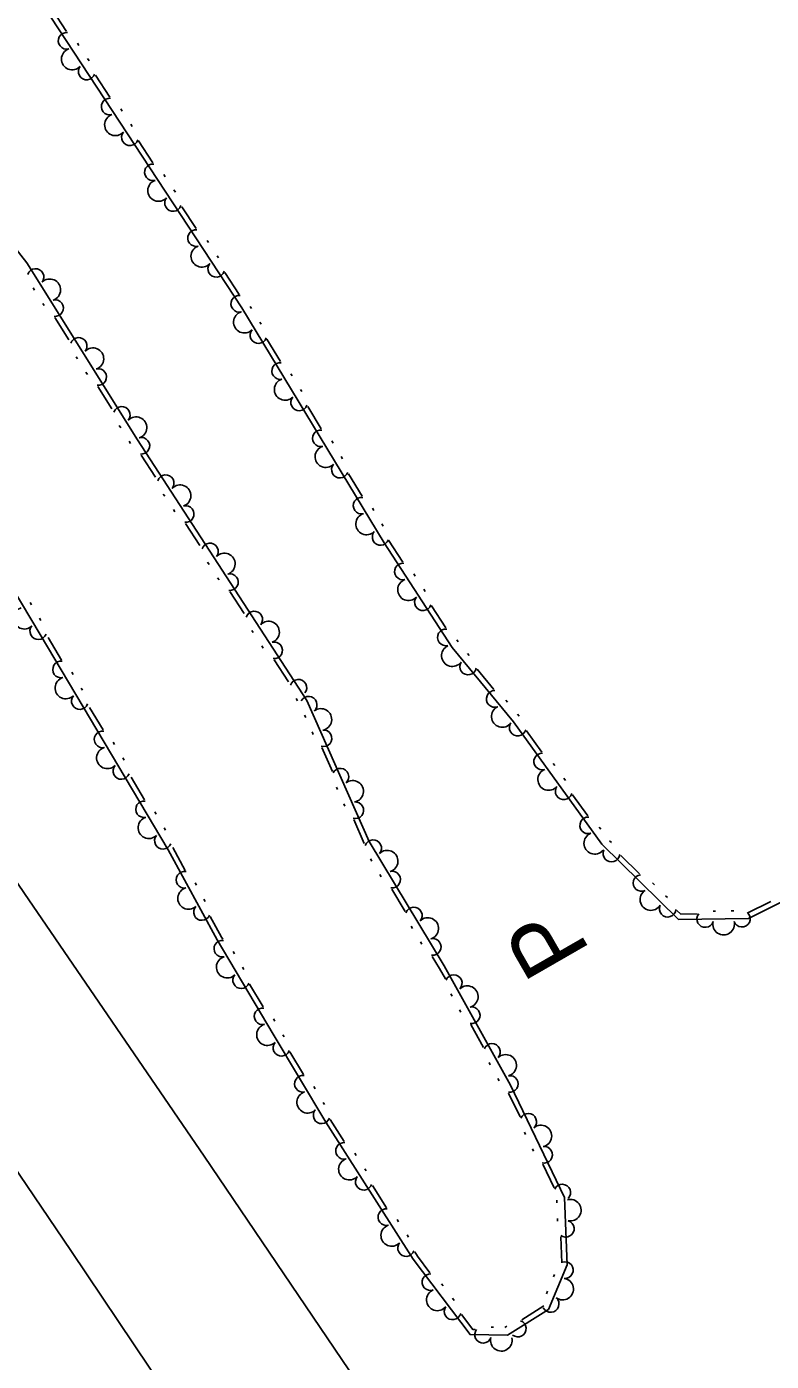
# Model space of a CAD drawing. Extents: x 2030130 to 2036320, y 723205 to 762423.
# Drawn here: x 2034304.6 to 2034421.1, y 759843.4 to 760052.2 of the extents above; entities that cross this region are included whole.
import ezdxf

# ---------------------------------------------------------------- set-up
doc = ezdxf.new("R2010")
doc.units = 0
for name, color, linetype in [('Draft_Station Labels Major', 7, 'Continuous'), ('Draft_Station Tics Major', 7, 'Continuous'), ('Prop Horizontal Alignment Ramp', 7, 'Continuous')]:
    doc.layers.add(name, color=color, linetype=linetype)

msp = doc.modelspace()

# ---------------------------------------------------------------- linework, layer by layer
at = {"layer": 'Draft_Station Labels Major'}
for p, q in [((2034332.4, 759875.51), (2034360.74, 759833.62)), ((2034311.52, 759860.74), (2034339.29, 759819.51))]:
    msp.add_line(p, q, dxfattribs=at)
for points in [[(2033718.38, 760730.67), (2033746.51, 760689.6), (2033774.62, 760648.49), (2033802.7, 760607.26), (2033830.67, 760566.06), (2033858.89, 760525.01), (2033886.8, 760483.79), (2033914.88, 760442.66), (2033945.45, 760397.69), (2033973.64, 760356.6), (2034001.68, 760315.42), (2034029.6, 760274.28), (2034057.68, 760233.24), (2034085.75, 760192.04), (2034113.77, 760150.87), (2034141.95, 760109.94), (2034159.83, 760083.11), (2034175.33, 760060.45), (2034197.95, 760027.35), (2034226.1, 759986.31), (2034253.95, 759945.01), (2034282.77, 759903.21), (2034311.52, 759860.74)], [(2034332.4, 759875.51), (2034304.28, 759916.6), (2034275.65, 759958.8), (2034247.14, 760000.6), (2034219.84, 760040.78), (2034191.61, 760081.68), (2034163.74, 760123.03), (2034135.88, 760163.98), (2034107.11, 760206.11), (2034080.34, 760245.23), (2034051.49, 760287.62), (2034022.91, 760329.48), (2033995.09, 760369.99), (2033966.89, 760411.11), (2033935.74, 760457.29), (2033907.97, 760498.26), (2033880.46, 760539.38), (2033851.33, 760582.23)]]:
    msp.add_lwpolyline(points, dxfattribs=at)
at = {"layer": 'Draft_Station Tics Major'}
for points in [[(2033865.22, 760655.09), (2033891.74, 760610.39), (2033928.27, 760560.61), (2033957.26, 760512.4), (2033990.84, 760466.46), (2034027.29, 760415.57), (2034062.79, 760367.8), (2034100.45, 760308.07), (2034126.3, 760269.13), (2034147.67, 760241.66), (2034171.15, 760213.5), (2034188.43, 760192.75), (2034201.98, 760164.61), (2034214.77, 760146.29), (2034228.35, 760126.12), (2034239.08, 760107.39), (2034248.43, 760090.51), (2034260.06, 760075.4), (2034270.93, 760058.37), (2034285.47, 760039.75), (2034304.65, 760015.27), (2034321.95, 759987.59), (2034348.43, 759946.8)], [(2033965.52, 760565.2), (2033991.66, 760525.26), (2034035.33, 760466.26), (2034077.67, 760405.45), (2034116.64, 760339.6), (2034163.46, 760272.17), (2034200.03, 760218.19), (2034231.88, 760166.87), (2034275.46, 760103.32), (2034304.79, 760059.28), (2034338.27, 760008.25), (2034360.54, 759971.46)], [(2034326.75, 759923.45), (2034306.73, 759957.16), (2034295.18, 759976.5), (2034283.32, 759994.79), (2034271.8, 760013.59), (2034263.7, 760033.69), (2034251.35, 760054.43), (2034226.75, 760080.43), (2034216.04, 760102), (2034205.31, 760120.49), (2034188.73, 760144.18), (2034176.71, 760159.19)], [(2034308.62, 760054.93), (2034310.87, 760051.5)], [(2034312.57, 760049.67), (2034312.79, 760049.32)], [(2034360.54, 759971.46), (2034371.18, 759955.13), (2034380.75, 759943.47), (2034394.56, 759924.33), (2034406.56, 759912.57), (2034417.47, 759912.7), (2034428.08, 759918.01), (2034440.63, 759926.81), (2034450.23, 759943), (2034456.78, 759958.6), (2034460.68, 759978.63), (2034471.11, 759991.86), (2034494.44, 760007.17), (2034510.43, 760028.22), (2034523.34, 760037.05), (2034542.05, 760043.12), (2034564.16, 760048.88), (2034589.7, 760042.02), (2034611.85, 760032.5), (2034630.07, 760020.88), (2034650.14, 760012.08), (2034662.68, 760016.57)], [(2034314.14, 760047.27), (2034314.37, 760046.92)], [(2034315.37, 760044.64), (2034317.62, 760041.21)], [(2034319.32, 760039.38), (2034319.54, 760039.04)], [(2034320.89, 760036.98), (2034321.12, 760036.64)], [(2034322.12, 760034.36), (2034324.37, 760030.93)], [(2034326.06, 760029.1), (2034326.29, 760028.75)], [(2034327.64, 760026.7), (2034327.87, 760026.35)], [(2034328.87, 760024.07), (2034331.12, 760020.64)], [(2034332.82, 760018.81), (2034333.04, 760018.47)], [(2034334.39, 760016.41), (2034334.62, 760016.06)], [(2034335.62, 760013.78), (2034337.87, 760010.36)], [(2034305.63, 760011.38), (2034305.85, 760011.03)], [(2034307.16, 760008.94), (2034307.37, 760008.6)], [(2034339.57, 760008.48), (2034339.79, 760008.12)], [(2034309.02, 760006.73), (2034311.2, 760003.25)], [(2034341.06, 760006.02), (2034341.27, 760005.67)], [(2034342.2, 760003.35), (2034344.32, 759999.84)], [(2034312.37, 760000.6), (2034312.59, 760000.25)], [(2034313.89, 759998.16), (2034314.11, 759997.82)], [(2034345.94, 759997.95), (2034346.16, 759997.6)], [(2034315.76, 759995.95), (2034317.94, 759992.47)], [(2034347.43, 759995.49), (2034347.64, 759995.14)], [(2034348.57, 759992.83), (2034350.69, 759989.32)], [(2034319.11, 759989.82), (2034319.33, 759989.47)], [(2034352.32, 759987.42), (2034352.53, 759987.07)], [(2034320.63, 759987.38), (2034320.85, 759987.04)], [(2034322.54, 759985.18), (2034324.78, 759981.74)], [(2034353.8, 759984.97), (2034354.01, 759984.62)], [(2034354.94, 759982.3), (2034357.06, 759978.79)], [(2034325.99, 759979.11), (2034326.22, 759978.76)], [(2034327.56, 759976.7), (2034327.78, 759976.35)], [(2034358.68, 759976.9), (2034358.9, 759976.55)], [(2034329.46, 759974.51), (2034331.7, 759971.07)], [(2034360.17, 759974.44), (2034360.38, 759974.09)], [(2034361.22, 759971.91), (2034363.46, 759968.47)], [(2034332.92, 759968.44), (2034333.14, 759968.1)], [(2034365.15, 759966.64), (2034365.37, 759966.29)], [(2034334.48, 759966.03), (2034334.7, 759965.69)], [(2034336.39, 759963.85), (2034338.62, 759960.41)], [(2034366.72, 759964.23), (2034366.94, 759963.89)], [(2034305.39, 759961.8), (2034305.18, 759962.15)], [(2034367.94, 759961.6), (2034370.18, 759958.17)], [(2034306.86, 759959.34), (2034306.65, 759959.69)], [(2034310.07, 759953.13), (2034307.98, 759956.66)], [(2034339.84, 759957.78), (2034340.06, 759957.43)], [(2034371.87, 759956.33), (2034372.09, 759955.99)], [(2034341.4, 759955.37), (2034341.62, 759955.02)], [(2034373.56, 759954.18), (2034373.82, 759953.86)], [(2034343.31, 759953.18), (2034345.54, 759949.74)], [(2034311.89, 759950.87), (2034311.68, 759951.23)], [(2034375.06, 759951.7), (2034377.66, 759948.53)], [(2034313.36, 759948.41), (2034313.15, 759948.76)], [(2034316.57, 759942.2), (2034314.47, 759945.73)], [(2034326.75, 759923.45), (2034334.39, 759909.37), (2034343.19, 759894.61), (2034351.39, 759880.82), (2034365.04, 759859.43), (2034373.96, 759847.6), (2034379.81, 759847.52), (2034386.21, 759851.55), (2034389.14, 759858.53), (2034388.74, 759869.08), (2034380.29, 759886.64), (2034369.91, 759905.3), (2034358.16, 759924.77), (2034348.43, 759946.8)], [(2034346.76, 759947.11), (2034346.98, 759946.77)], [(2034379.54, 759946.89), (2034379.8, 759946.57)], [(2034348.26, 759944.15), (2034348.09, 759944.52)], [(2034381.36, 759944.67), (2034381.62, 759944.35)], [(2034349.41, 759941.52), (2034349.25, 759941.9)], [(2034382.78, 759942.06), (2034385.18, 759938.73)], [(2034318.38, 759939.95), (2034318.17, 759940.3)], [(2034352.44, 759935.69), (2034350.78, 759939.44)], [(2034319.85, 759937.48), (2034319.64, 759937.83)], [(2034386.95, 759936.98), (2034387.19, 759936.65)], [(2034323.06, 759931.27), (2034320.97, 759934.8)], [(2034353.23, 759932.9), (2034353.06, 759933.27)], [(2034388.63, 759934.65), (2034388.87, 759934.32)], [(2034389.98, 759932.08), (2034392.38, 759928.76)], [(2034324.88, 759929.02), (2034324.67, 759929.37)], [(2034354.39, 759930.27), (2034354.22, 759930.65)], [(2034326.35, 759926.55), (2034326.14, 759926.9)], [(2034357.42, 759924.44), (2034355.76, 759928.19)], [(2034394.15, 759927), (2034394.39, 759926.67)], [(2034395.75, 759924.88), (2034396.05, 759924.6)], [(2034327.48, 759923.84), (2034329.43, 759920.24)], [(2034358.6, 759921.67), (2034358.38, 759922.03)], [(2034397.52, 759922.58), (2034400.45, 759919.71)], [(2034360.08, 759919.22), (2034359.87, 759919.57)], [(2034330.96, 759918.27), (2034331.16, 759917.91)], [(2034363.82, 759913.81), (2034361.7, 759917.32)], [(2034402.49, 759918.28), (2034402.78, 759917.99)], [(2034332.33, 759915.74), (2034332.53, 759915.39)], [(2034404.54, 759916.27), (2034404.83, 759915.98)], [(2034417.31, 759913.53), (2034420.97, 759915.37)], [(2034333.34, 759913.03), (2034335.1, 759909.78), (2034335.29, 759909.46)], [(2034406.3, 759913.97), (2034406.89, 759913.39), (2034409.49, 759913.42)], [(2034411.95, 759913.86), (2034412.36, 759913.87)], [(2034414.81, 759913.89), (2034415.22, 759913.9)], [(2034364.95, 759911.14), (2034364.74, 759911.49)], [(2034366.43, 759908.68), (2034366.22, 759909.03)], [(2034336.91, 759907.56), (2034337.11, 759907.2)], [(2034370.1, 759903.26), (2034369.2, 759904.89), (2034368.05, 759906.78)], [(2034338.38, 759905.09), (2034338.59, 759904.74)], [(2034339.49, 759902.41), (2034341.59, 759898.89)], [(2034371.14, 759900.56), (2034370.94, 759900.91)], [(2034372.53, 759898.05), (2034372.33, 759898.4)], [(2034343.2, 759896.99), (2034343.41, 759896.64)], [(2034376.08, 759892.51), (2034374.09, 759896.1)], [(2034344.67, 759894.52), (2034344.88, 759894.17)], [(2034345.79, 759891.84), (2034347.89, 759888.32)], [(2034377.12, 759889.8), (2034376.92, 759890.16)], [(2034378.52, 759887.3), (2034378.32, 759887.66)], [(2034349.5, 759886.41), (2034349.71, 759886.06)], [(2034381.77, 759881.67), (2034379.99, 759885.36)], [(2034350.96, 759883.94), (2034351.17, 759883.59)], [(2034352.09, 759881.25), (2034354.27, 759877.83)], [(2034382.65, 759878.9), (2034382.47, 759879.27)], [(2034355.94, 759875.98), (2034356.16, 759875.63)], [(2034383.89, 759876.32), (2034383.72, 759876.69)], [(2034357.48, 759873.56), (2034357.7, 759873.21)], [(2034387.11, 759870.58), (2034385.33, 759874.28)], [(2034358.68, 759870.92), (2034360.89, 759867.46)], [(2034387.54, 759868.22), (2034387.53, 759868.63)], [(2034362.56, 759865.61), (2034362.78, 759865.26)], [(2034387.65, 759865.35), (2034387.64, 759865.76)], [(2034364.1, 759863.19), (2034364.32, 759862.84)], [(2034388.31, 759858.81), (2034388.16, 759862.91)], [(2034365.3, 759860.55), (2034365.72, 759859.9), (2034367.68, 759857.29)], [(2034387.02, 759856.65), (2034387.18, 759857.03)], [(2034369.49, 759855.57), (2034369.74, 759855.25)], [(2034385.91, 759854), (2034386.06, 759854.38)], [(2034371.22, 759853.28), (2034371.47, 759852.95)], [(2034382.03, 759849.89), (2034385.5, 759852.08)], [(2034372.62, 759850.74), (2034374.38, 759848.42), (2034374.77, 759848.41)], [(2034377.23, 759848.79), (2034377.64, 759848.78)], [(2034379.39, 759848.71), (2034379.73, 759848.93)]]:
    msp.add_lwpolyline(points, dxfattribs=at)
for centre, radius, start, end in [((2034310.86, 760050.02), 1.3, 84.0412, 284.8378), ((2034311.75, 760047.17), 1.69, 109.2365, 317.309), ((2034314.01, 760045.22), 1.3, 141.7077, 342.5043), ((2034317.61, 760039.74), 1.3, 84.0412, 284.8378), ((2034318.5, 760036.88), 1.69, 109.2365, 317.309), ((2034320.76, 760034.93), 1.3, 141.7077, 342.5043), ((2034324.36, 760029.45), 1.3, 84.0412, 284.8378), ((2034325.25, 760026.6), 1.69, 109.2365, 317.309), ((2034327.51, 760024.65), 1.3, 141.7077, 342.5043), ((2034331.11, 760019.16), 1.3, 84.0412, 284.8378), ((2034332, 760016.31), 1.69, 109.2365, 317.309), ((2034334.26, 760014.36), 1.3, 141.7077, 342.5043), ((2034306.02, 760013.07), 1.3, 320.4469, 161.2435), ((2034308.24, 760011.07), 1.69, 287.9757, 136.0482), ((2034309.07, 760008.21), 1.3, 262.7804, 103.577), ((2034337.86, 760008.88), 1.3, 84.0412, 284.8378), ((2034338.67, 760006.01), 1.69, 107.1434, 315.2159), ((2034340.86, 760003.98), 1.3, 139.6146, 340.4112), ((2034312.76, 760002.29), 1.3, 320.4469, 161.2435), ((2034314.98, 760000.29), 1.69, 287.9757, 136.0482), ((2034315.81, 759997.43), 1.3, 262.7804, 103.577), ((2034344.25, 759998.36), 1.3, 81.9481, 282.7447), ((2034345.04, 759995.48), 1.69, 107.1434, 315.2159), ((2034347.23, 759993.45), 1.3, 139.6146, 340.4112), ((2034319.5, 759991.51), 1.3, 320.4469, 161.2435), ((2034321.72, 759989.51), 1.69, 287.9757, 136.0482), ((2034322.56, 759986.66), 1.3, 263.7522, 104.5488), ((2034350.62, 759987.84), 1.3, 81.9481, 282.7447), ((2034351.41, 759984.96), 1.69, 107.1434, 315.2159), ((2034353.6, 759982.93), 1.3, 139.6146, 340.4112), ((2034326.36, 759980.81), 1.3, 321.4187, 162.2153), ((2034328.61, 759978.85), 1.69, 288.9475, 137.02), ((2034329.48, 759975.99), 1.3, 263.7522, 104.5488), ((2034356.99, 759977.31), 1.3, 81.9481, 282.7447), ((2034357.78, 759974.43), 1.69, 107.1434, 315.2159), ((2034359.97, 759972.4), 1.3, 139.6146, 340.4112), ((2034333.28, 759970.14), 1.3, 321.4187, 162.2153), ((2034335.53, 759968.18), 1.69, 288.9475, 137.02), ((2034336.4, 759965.33), 1.3, 263.7522, 104.5488), ((2034363.45, 759966.99), 1.3, 83.8727, 284.6693), ((2034364.33, 759964.14), 1.69, 109.068, 317.1405), ((2034366.58, 759962.18), 1.3, 141.5392, 342.3358), ((2034304.26, 759959.69), 1.69, 106.7887, 314.8612), ((2034340.2, 759959.48), 1.3, 321.4187, 162.2153), ((2034306.43, 759957.65), 1.3, 139.2599, 340.0564), ((2034342.45, 759957.52), 1.69, 288.9475, 137.02), ((2034370.17, 759956.69), 1.3, 83.8727, 284.6693), ((2034343.32, 759954.66), 1.3, 263.7522, 104.5488), ((2034371.19, 759953.83), 1.69, 115.3331, 323.4056), ((2034310, 759951.66), 1.3, 81.484, 282.2805), ((2034373.65, 759952.13), 1.3, 147.8043, 348.6009), ((2034310.76, 759948.77), 1.69, 106.6792, 314.7517), ((2034347.12, 759948.81), 1.3, 321.4187, 162.2153), ((2034377.81, 759947.06), 1.3, 90.1379, 290.9344), ((2034312.93, 759946.72), 1.3, 139.1504, 339.947), ((2034348.72, 759946.15), 1.3, 312.2827, 153.0793), ((2034378.99, 759944.32), 1.69, 115.3331, 323.4056), ((2034350.63, 759943.85), 1.69, 279.8115, 127.884), ((2034316.49, 759940.73), 1.3, 81.484, 282.2805), ((2034351.04, 759940.9), 1.3, 254.6163, 95.4128), ((2034381.4, 759942.58), 1.3, 144.2435, 345.0401), ((2034317.25, 759937.84), 1.69, 106.6792, 314.7517), ((2034385.23, 759937.26), 1.3, 86.5771, 287.3736), ((2034319.42, 759935.79), 1.3, 139.1504, 339.947), ((2034353.69, 759934.89), 1.3, 312.2827, 153.0793), ((2034386.25, 759934.45), 1.69, 111.7723, 319.8448), ((2034355.6, 759932.6), 1.69, 279.8115, 127.884), ((2034388.59, 759932.6), 1.3, 144.2435, 345.0401), ((2034322.98, 759929.8), 1.3, 81.484, 282.2805), ((2034356.01, 759929.64), 1.3, 254.6163, 95.4128), ((2034323.74, 759926.91), 1.69, 106.6792, 314.7517), ((2034392.43, 759927.28), 1.3, 86.5771, 287.3736), ((2034325.92, 759924.86), 1.3, 139.1504, 339.947), ((2034358.8, 759923.71), 1.3, 319.5213, 160.3179), ((2034393.45, 759924.47), 1.69, 111.7723, 319.8448), ((2034360.99, 759921.68), 1.69, 287.0501, 135.1226), ((2034396.06, 759922.86), 1.3, 154.0103, 354.8069), ((2034329.3, 759918.76), 1.3, 79.2443, 280.0409), ((2034361.77, 759918.8), 1.3, 261.8549, 102.6514), ((2034400.75, 759918.26), 1.3, 96.3438, 297.1404), ((2034329.94, 759915.85), 1.69, 104.4396, 312.5121), ((2034402.23, 759915.67), 1.69, 121.5391, 329.6116), ((2034332.03, 759913.72), 1.3, 136.9108, 337.7073), ((2034365.16, 759913.18), 1.3, 319.5213, 160.3179), ((2034404.85, 759914.24), 1.3, 154.0103, 354.8069), ((2034367.34, 759911.14), 1.69, 287.0501, 135.1226), ((2034410.73, 759912.62), 1.3, 141.4359, 342.2325), ((2034413.61, 759911.83), 1.69, 166.6312, 14.7036), ((2034416.47, 759912.68), 1.3, 199.1024, 39.8989), ((2034335.22, 759907.98), 1.3, 81.5644, 282.3609), ((2034368.12, 759908.26), 1.3, 261.8549, 102.6514), ((2034335.98, 759905.1), 1.69, 106.7596, 314.8321), ((2034338.16, 759903.05), 1.3, 139.2308, 340.0274), ((2034371.41, 759902.59), 1.3, 317.5297, 158.3263), ((2034373.53, 759900.48), 1.69, 285.0585, 133.131), ((2034341.52, 759897.41), 1.3, 81.5644, 282.3609), ((2034374.21, 759897.57), 1.3, 259.8633, 100.6598), ((2034342.28, 759894.53), 1.69, 106.7596, 314.8321), ((2034344.46, 759892.48), 1.3, 139.1766, 339.9732), ((2034377.4, 759891.84), 1.3, 317.5297, 158.3263), ((2034379.51, 759889.73), 1.69, 285.0585, 133.131), ((2034347.81, 759886.84), 1.3, 81.5102, 282.3067), ((2034380.19, 759886.82), 1.3, 259.8633, 100.6598), ((2034348.57, 759883.95), 1.69, 106.7054, 314.7779), ((2034350.74, 759881.91), 1.3, 139.1766, 339.9732), ((2034383.05, 759880.91), 1.3, 314.1382, 154.9348), ((2034385.03, 759878.68), 1.69, 281.667, 129.7395), ((2034354.24, 759876.35), 1.3, 83.3145, 284.1111), ((2034385.54, 759875.74), 1.3, 256.4718, 97.2683), ((2034355.09, 759873.49), 1.69, 108.5098, 316.5823), ((2034357.33, 759871.51), 1.3, 140.981, 341.7776), ((2034388.38, 759869.83), 1.3, 314.1382, 154.9348), ((2034389.64, 759867.07), 1.69, 258.1412, 106.2137), ((2034360.86, 759865.98), 1.3, 83.3145, 284.1111), ((2034361.71, 759863.12), 1.69, 108.5098, 316.5823), ((2034388.93, 759864.17), 1.3, 232.9459, 73.7425), ((2034363.95, 759861.14), 1.3, 140.981, 341.7776), ((2034388.79, 759857.69), 1.3, 265.6173, 106.4138), ((2034367.77, 759855.81), 1.3, 87.8065, 288.6031), ((2034388.43, 759854.72), 1.69, 233.1461, 81.2186), ((2034368.84, 759853.03), 1.69, 113.0018, 321.0743), ((2034371.23, 759851.23), 1.3, 145.473, 346.2696), ((2034386.56, 759852.39), 1.3, 207.9508, 48.7474), ((2034381.43, 759848.54), 1.3, 230.6542, 71.4508), ((2034375.98, 759847.58), 1.3, 139.932, 340.7286), ((2034378.84, 759846.71), 1.69, 165.1273, 13.1998)]:
    msp.add_arc(centre, radius, start, end, dxfattribs=at)

# ---------------------------------------------------------------- texts
at = {"layer": 'Prop Horizontal Alignment Ramp'}
msp.add_text('P', height=10.66, rotation=119.9336, dxfattribs=at).set_placement((2034392.87, 759907.56))

doc.saveas('drawing.dxf')
